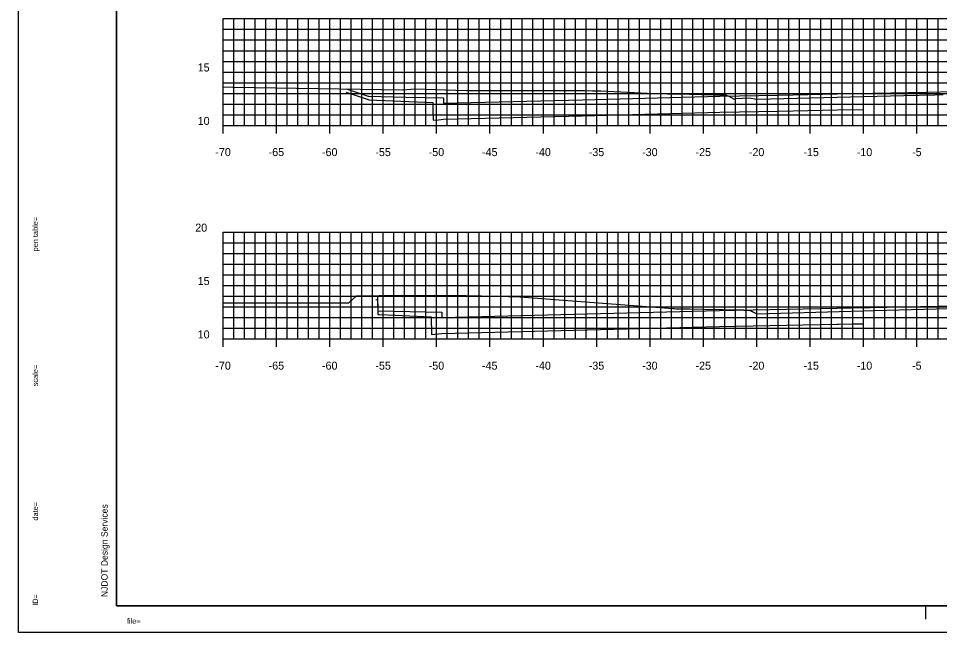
# Model space of a CAD drawing. Extents: x 40011 to 50684, y 49949 to 72236.
# Drawn here: x 42164.4 to 42250.7, y 68071.1 to 68128.6 of the extents above; entities that cross this region are included whole.
import ezdxf

# ---------------------------------------------------------------- set-up
doc = ezdxf.new("R2010")
doc.units = 0
for name, color, linetype in [('1', 7, 'Continuous'), ('41', 7, 'Continuous'), ('51', 7, 'Continuous'), ('52', 7, 'Continuous'), ('53', 7, 'Continuous'), ('54', 7, 'Continuous'), ('55', 7, 'Continuous'), ('57', 7, 'Continuous'), ('58', 7, 'Continuous'), ('59', 7, 'Continuous')]:
    doc.layers.add(name, color=color, linetype=linetype)

msp = doc.modelspace()

# ---------------------------------------------------------------- linework, layer by layer
at = {"layer": '1'}
for p, q in [((42173.586, 68178.597), (42173.586, 68073.597)), ((42173.586, 68073.597), (42338.586, 68073.597)), ((42249.42, 68072.347), (42249.42, 68073.597)), ((42339.087, 68071.097), (42164.392, 68071.097))]:
    msp.add_line(p, q, dxfattribs=at)
at = {"layer": '41'}
for points in [[(42164.392, 68181.097), (42339.087, 68181.097), (42339.087, 68071.097), (42164.392, 68071.097)], [(42173.586, 68178.597), (42338.586, 68178.597), (42338.586, 68073.597), (42173.586, 68073.597)]]:
    msp.add_lwpolyline(points, close=True, dxfattribs=at)
at = {"layer": '51'}
for p, q in [((42183.586, 68118.597), (42183.586, 68128.597)), ((42183.586, 68128.597), (42184.336, 68128.597)), ((42183.586, 68123.597), (42184.336, 68123.597)), ((42183.586, 68118.597), (42184.336, 68118.597)), ((42183.586, 68098.597), (42183.586, 68108.597)), ((42183.586, 68108.597), (42184.336, 68108.597)), ((42183.586, 68103.597), (42184.336, 68103.597)), ((42183.586, 68098.597), (42184.336, 68098.597))]:
    msp.add_line(p, q, dxfattribs=at)
at = {"layer": '52'}
for p, q in [((42183.586, 68118.597), (42323.586, 68118.597)), ((42183.586, 68117.847), (42183.586, 68118.597)), ((42188.586, 68117.847), (42188.586, 68118.597)), ((42193.586, 68117.847), (42193.586, 68118.597)), ((42198.586, 68117.847), (42198.586, 68118.597)), ((42203.586, 68117.847), (42203.586, 68118.597)), ((42208.586, 68117.847), (42208.586, 68118.597)), ((42213.586, 68117.847), (42213.586, 68118.597)), ((42218.586, 68117.847), (42218.586, 68118.597)), ((42223.586, 68117.847), (42223.586, 68118.597)), ((42228.586, 68117.847), (42228.586, 68118.597)), ((42233.586, 68117.847), (42233.586, 68118.597)), ((42238.586, 68117.847), (42238.586, 68118.597)), ((42243.586, 68117.847), (42243.586, 68118.597)), ((42248.586, 68117.847), (42248.586, 68118.597)), ((42183.586, 68098.597), (42323.586, 68098.597)), ((42183.586, 68097.847), (42183.586, 68098.597)), ((42188.586, 68097.847), (42188.586, 68098.597)), ((42193.586, 68097.847), (42193.586, 68098.597)), ((42198.586, 68097.847), (42198.586, 68098.597)), ((42203.586, 68097.847), (42203.586, 68098.597)), ((42208.586, 68097.847), (42208.586, 68098.597)), ((42213.586, 68097.847), (42213.586, 68098.597)), ((42218.586, 68097.847), (42218.586, 68098.597)), ((42223.586, 68097.847), (42223.586, 68098.597)), ((42228.586, 68097.847), (42228.586, 68098.597)), ((42233.586, 68097.847), (42233.586, 68098.597)), ((42238.586, 68097.847), (42238.586, 68098.597)), ((42243.586, 68097.847), (42243.586, 68098.597)), ((42248.586, 68097.847), (42248.586, 68098.597))]:
    msp.add_line(p, q, dxfattribs=at)
at = {"layer": '53'}
for p, q in [((42183.586, 68127.597), (42323.586, 68127.597)), ((42183.586, 68126.597), (42323.586, 68126.597)), ((42183.586, 68125.597), (42323.586, 68125.597)), ((42183.586, 68124.597), (42323.586, 68124.597)), ((42183.586, 68122.597), (42323.586, 68122.597)), ((42183.586, 68121.597), (42323.586, 68121.597)), ((42183.586, 68120.597), (42323.586, 68120.597)), ((42183.586, 68119.597), (42323.586, 68119.597)), ((42183.586, 68107.597), (42323.586, 68107.597)), ((42183.586, 68106.597), (42323.586, 68106.597)), ((42183.586, 68105.597), (42323.586, 68105.597)), ((42183.586, 68104.597), (42323.586, 68104.597)), ((42183.586, 68102.597), (42323.586, 68102.597)), ((42183.586, 68101.597), (42323.586, 68101.597)), ((42183.586, 68100.597), (42323.586, 68100.597)), ((42183.586, 68099.597), (42323.586, 68099.597))]:
    msp.add_line(p, q, dxfattribs=at)
at = {"layer": '54'}
for p, q in [((42184.586, 68118.597), (42184.586, 68128.597)), ((42185.586, 68118.597), (42185.586, 68128.597)), ((42186.586, 68118.597), (42186.586, 68128.597)), ((42187.586, 68118.597), (42187.586, 68128.597)), ((42189.586, 68118.597), (42189.586, 68128.597)), ((42190.586, 68118.597), (42190.586, 68128.597)), ((42191.586, 68118.597), (42191.586, 68128.597)), ((42192.586, 68118.597), (42192.586, 68128.597)), ((42194.586, 68118.597), (42194.586, 68128.597)), ((42195.586, 68118.597), (42195.586, 68128.597)), ((42196.586, 68118.597), (42196.586, 68128.597)), ((42197.586, 68118.597), (42197.586, 68128.597)), ((42199.586, 68118.597), (42199.586, 68128.597)), ((42200.586, 68118.597), (42200.586, 68128.597)), ((42201.586, 68118.597), (42201.586, 68128.597)), ((42202.586, 68118.597), (42202.586, 68128.597)), ((42204.586, 68118.597), (42204.586, 68128.597)), ((42205.586, 68118.597), (42205.586, 68128.597)), ((42206.586, 68118.597), (42206.586, 68128.597)), ((42207.586, 68118.597), (42207.586, 68128.597)), ((42209.586, 68118.597), (42209.586, 68128.597)), ((42210.586, 68118.597), (42210.586, 68128.597)), ((42211.586, 68118.597), (42211.586, 68128.597)), ((42212.586, 68118.597), (42212.586, 68128.597)), ((42214.586, 68118.597), (42214.586, 68128.597)), ((42215.586, 68118.597), (42215.586, 68128.597)), ((42216.586, 68118.597), (42216.586, 68128.597)), ((42217.586, 68118.597), (42217.586, 68128.597)), ((42219.586, 68118.597), (42219.586, 68128.597)), ((42220.586, 68118.597), (42220.586, 68128.597)), ((42221.586, 68118.597), (42221.586, 68128.597)), ((42222.586, 68118.597), (42222.586, 68128.597)), ((42224.586, 68118.597), (42224.586, 68128.597)), ((42225.586, 68118.597), (42225.586, 68128.597)), ((42226.586, 68118.597), (42226.586, 68128.597)), ((42227.586, 68118.597), (42227.586, 68128.597)), ((42229.586, 68118.597), (42229.586, 68128.597)), ((42230.586, 68118.597), (42230.586, 68128.597)), ((42231.586, 68118.597), (42231.586, 68128.597)), ((42232.586, 68118.597), (42232.586, 68128.597)), ((42234.586, 68118.597), (42234.586, 68128.597)), ((42235.586, 68118.597), (42235.586, 68128.597)), ((42236.586, 68118.597), (42236.586, 68128.597)), ((42237.586, 68118.597), (42237.586, 68128.597)), ((42239.586, 68118.597), (42239.586, 68128.597)), ((42240.586, 68118.597), (42240.586, 68128.597)), ((42241.586, 68118.597), (42241.586, 68128.597)), ((42242.586, 68118.597), (42242.586, 68128.597)), ((42244.586, 68118.597), (42244.586, 68128.597)), ((42245.586, 68118.597), (42245.586, 68128.597)), ((42246.586, 68118.597), (42246.586, 68128.597)), ((42247.586, 68118.597), (42247.586, 68128.597)), ((42249.586, 68118.597), (42249.586, 68128.597)), ((42250.586, 68118.597), (42250.586, 68128.597)), ((42184.586, 68098.597), (42184.586, 68108.597)), ((42185.586, 68098.597), (42185.586, 68108.597)), ((42186.586, 68098.597), (42186.586, 68108.597)), ((42187.586, 68098.597), (42187.586, 68108.597)), ((42189.586, 68098.597), (42189.586, 68108.597)), ((42190.586, 68098.597), (42190.586, 68108.597)), ((42191.586, 68098.597), (42191.586, 68108.597)), ((42192.586, 68098.597), (42192.586, 68108.597)), ((42194.586, 68098.597), (42194.586, 68108.597)), ((42195.586, 68098.597), (42195.586, 68108.597)), ((42196.586, 68098.597), (42196.586, 68108.597)), ((42197.586, 68098.597), (42197.586, 68108.597)), ((42199.586, 68098.597), (42199.586, 68108.597)), ((42200.586, 68098.597), (42200.586, 68108.597)), ((42201.586, 68098.597), (42201.586, 68108.597)), ((42202.586, 68098.597), (42202.586, 68108.597)), ((42204.586, 68098.597), (42204.586, 68108.597)), ((42205.586, 68098.597), (42205.586, 68108.597)), ((42206.586, 68098.597), (42206.586, 68108.597)), ((42207.586, 68098.597), (42207.586, 68108.597)), ((42209.586, 68098.597), (42209.586, 68108.597)), ((42210.586, 68098.597), (42210.586, 68108.597)), ((42211.586, 68098.597), (42211.586, 68108.597)), ((42212.586, 68098.597), (42212.586, 68108.597)), ((42214.586, 68098.597), (42214.586, 68108.597)), ((42215.586, 68098.597), (42215.586, 68108.597)), ((42216.586, 68098.597), (42216.586, 68108.597)), ((42217.586, 68098.597), (42217.586, 68108.597)), ((42219.586, 68098.597), (42219.586, 68108.597)), ((42220.586, 68098.597), (42220.586, 68108.597)), ((42221.586, 68098.597), (42221.586, 68108.597)), ((42222.586, 68098.597), (42222.586, 68108.597)), ((42224.586, 68098.597), (42224.586, 68108.597)), ((42225.586, 68098.597), (42225.586, 68108.597)), ((42226.586, 68098.597), (42226.586, 68108.597)), ((42227.586, 68098.597), (42227.586, 68108.597)), ((42229.586, 68098.597), (42229.586, 68108.597)), ((42230.586, 68098.597), (42230.586, 68108.597)), ((42231.586, 68098.597), (42231.586, 68108.597)), ((42232.586, 68098.597), (42232.586, 68108.597)), ((42234.586, 68098.597), (42234.586, 68108.597)), ((42235.586, 68098.597), (42235.586, 68108.597)), ((42236.586, 68098.597), (42236.586, 68108.597)), ((42237.586, 68098.597), (42237.586, 68108.597)), ((42239.586, 68098.597), (42239.586, 68108.597)), ((42240.586, 68098.597), (42240.586, 68108.597)), ((42241.586, 68098.597), (42241.586, 68108.597)), ((42242.586, 68098.597), (42242.586, 68108.597)), ((42244.586, 68098.597), (42244.586, 68108.597)), ((42245.586, 68098.597), (42245.586, 68108.597)), ((42246.586, 68098.597), (42246.586, 68108.597)), ((42247.586, 68098.597), (42247.586, 68108.597)), ((42249.586, 68098.597), (42249.586, 68108.597)), ((42250.586, 68098.597), (42250.586, 68108.597))]:
    msp.add_line(p, q, dxfattribs=at)
at = {"layer": '55'}
for p, q in [((42183.586, 68128.597), (42323.586, 68128.597)), ((42183.586, 68118.597), (42183.586, 68128.597)), ((42188.586, 68118.597), (42188.586, 68128.597)), ((42193.586, 68118.597), (42193.586, 68128.597)), ((42198.586, 68118.597), (42198.586, 68128.597)), ((42203.586, 68118.597), (42203.586, 68128.597)), ((42208.586, 68118.597), (42208.586, 68128.597)), ((42213.586, 68118.597), (42213.586, 68128.597)), ((42218.586, 68118.597), (42218.586, 68128.597)), ((42223.586, 68118.597), (42223.586, 68128.597)), ((42228.586, 68118.597), (42228.586, 68128.597)), ((42233.586, 68118.597), (42233.586, 68128.597)), ((42238.586, 68118.597), (42238.586, 68128.597)), ((42243.586, 68118.597), (42243.586, 68128.597)), ((42248.586, 68118.597), (42248.586, 68128.597)), ((42183.586, 68123.597), (42323.586, 68123.597)), ((42183.586, 68118.597), (42323.586, 68118.597)), ((42183.586, 68108.597), (42323.586, 68108.597)), ((42183.586, 68098.597), (42183.586, 68108.597)), ((42188.586, 68098.597), (42188.586, 68108.597)), ((42193.586, 68098.597), (42193.586, 68108.597)), ((42198.586, 68098.597), (42198.586, 68108.597)), ((42203.586, 68098.597), (42203.586, 68108.597)), ((42208.586, 68098.597), (42208.586, 68108.597)), ((42213.586, 68098.597), (42213.586, 68108.597)), ((42218.586, 68098.597), (42218.586, 68108.597)), ((42223.586, 68098.597), (42223.586, 68108.597)), ((42228.586, 68098.597), (42228.586, 68108.597)), ((42233.586, 68098.597), (42233.586, 68108.597)), ((42238.586, 68098.597), (42238.586, 68108.597)), ((42243.586, 68098.597), (42243.586, 68108.597)), ((42248.586, 68098.597), (42248.586, 68108.597)), ((42183.586, 68103.597), (42323.586, 68103.597)), ((42183.586, 68098.597), (42323.586, 68098.597))]:
    msp.add_line(p, q, dxfattribs=at)
at = {"layer": '57'}
for points in [[(42183.586, 68122.2), (42184.498, 68122.18), (42200.409, 68121.938), (42201.557, 68122.016), (42206.36, 68121.862), (42217.207, 68121.872), (42217.453, 68121.867), (42218.19, 68121.85), (42218.986, 68121.827), (42223.355, 68121.631), (42225.219, 68121.57), (42226.166, 68121.544), (42229.545, 68121.474), (42230.688, 68121.476), (42230.963, 68121.328), (42231.468, 68121.063), (42231.583, 68121.111), (42232.893, 68121.187), (42233.551, 68121.044), (42233.619, 68121.041), (42247.363, 68121.385), (42250.28, 68121.459), (42251.047, 68121.477)], [(42183.586, 68101.991), (42194.195, 68101.977), (42194.824, 68101.976), (42195.352, 68101.965), (42195.37, 68101.975), (42196.084, 68102.637), (42200.287, 68102.685), (42206.344, 68102.658), (42209.228, 68102.611), (42209.624, 68102.603), (42210.034, 68102.595), (42210.324, 68102.587), (42210.967, 68102.562), (42225.734, 68101.446), (42225.782, 68101.445), (42225.887, 68101.44), (42226.016, 68101.433), (42226.128, 68101.427), (42226.518, 68101.414), (42227.311, 68101.404), (42228.57, 68101.384), (42232.341, 68101.311), (42232.36, 68101.303), (42232.869, 68101.273), (42232.908, 68101.289), (42233.583, 68100.964), (42233.638, 68100.95), (42244.607, 68101.249), (42252.72, 68101.477)]]:
    msp.add_lwpolyline(points, dxfattribs=at)
at = {"layer": '58'}
for points in [[(42195.109, 68121.699), (42197.17, 68121.012), (42197.234, 68120.99), (42200.237, 68120.872), (42203.238, 68120.755), (42203.243, 68119.923), (42203.248, 68119.086), (42203.746, 68119.132), (42204.244, 68119.179), (42217.244, 68119.504), (42230.13, 68119.826), (42235.63, 68119.936), (42241.131, 68120.047), (42243.581, 68120.096), (42243.587, 68120.096)], [(42197.894, 68102.296), (42198.003, 68102.264), (42198.048, 68102.329), (42198.076, 68100.897), (42198.231, 68100.89), (42199.708, 68100.826), (42203.081, 68100.681), (42203.09, 68099.012), (42204.086, 68099.106), (42230.086, 68099.756), (42241.086, 68099.976), (42241.313, 68099.98), (42242.578, 68100.006), (42243.53, 68100.025), (42243.586, 68100.026), (42243.586, 68100.026), (42243.587, 68100.026)]]:
    msp.add_lwpolyline(points, dxfattribs=at)
at = {"layer": '59'}
for points in [[(42195.11, 68122.029), (42197.17, 68121.342), (42197.234, 68121.321), (42200.734, 68121.251), (42204.234, 68121.181), (42204.239, 68120.931), (42204.244, 68120.681), (42217.244, 68121.006), (42230.13, 68121.328), (42235.63, 68121.438), (42241.132, 68121.548), (42249.481, 68121.715), (42252.086, 68121.767)], [(42198.048, 68102.659), (42198.076, 68101.227), (42204.076, 68101.107), (42204.086, 68100.607), (42230.086, 68101.257), (42241.086, 68101.477), (42252.077, 68101.697), (42252.223, 68102.194), (42252.239, 68102.194), (42254.085, 68102.163), (42255.926, 68102.132), (42255.931, 68102.132), (42256.077, 68101.63), (42259.086, 68101.584), (42270.086, 68101.364), (42284.743, 68100.998), (42284.753, 68101.498), (42291.753, 68101.638), (42291.756, 68101.638), (42294.737, 68101.696), (42294.741, 68101.536), (42294.747, 68101.196)]]:
    msp.add_lwpolyline(points, dxfattribs=at)

# ---------------------------------------------------------------- texts
at = {"layer": '1'}
for s, height, rotation, p in [('...................pentable..................', 0.0072, 90, (42166.224, 68110.775)), ('pen table=', 0.5, 90, (42166.224, 68106.791)), ('......scale......', 0.0072, 90, (42166.224, 68096.608)), ('scale=', 0.5, 90, (42166.224, 68094.163)), ('.......time......', 0.0072, 90, (42166.224, 68083.775)), ('date=', 0.5, 90, (42166.224, 68081.587)), ('NJDOT Design Services', 0.6, 90, (42172.753, 68074.419)), ('............who............', 0.0072, 90, (42166.224, 68074.93)), ('ID=', 0.5, 90, (42166.224, 68073.601)), ('file=', 0.5, 360, (42174.56, 68071.93)), ('...................bob..................', 0.0072, 360, (42176.224, 68071.93))]:
    msp.add_text(s, height=height, rotation=rotation, dxfattribs=at).set_placement(p)
at = {"layer": '51'}
for s, height, p in [('15', 0.75, (42181.193, 68123.647)), ('10', 0.75, (42181.193, 68118.647)), ('-', 0.0001, (42183.586, 68118.597)), ('20', 0.75, (42180.966, 68108.647)), ('15', 0.75, (42181.193, 68103.647)), ('10', 0.75, (42181.193, 68098.647)), ('-', 0.0001, (42183.586, 68098.597))]:
    msp.add_text(s, height=height, dxfattribs=at).set_placement(p)
at = {"layer": '52'}
for s, p in [('-70', (42182.847, 68115.722)), ('-65', (42187.841, 68115.722)), ('-60', (42192.841, 68115.722)), ('-55', (42197.843, 68115.722)), ('-50', (42202.843, 68115.722)), ('-45', (42207.838, 68115.722)), ('-40', (42212.838, 68115.722)), ('-35', (42217.843, 68115.722)), ('-30', (42222.843, 68115.722)), ('-25', (42227.847, 68115.722)), ('-20', (42232.847, 68115.722)), ('-15', (42237.96, 68115.722)), ('-10', (42242.96, 68115.722)), ('-5', (42248.145, 68115.722)), ('-70', (42182.847, 68095.722)), ('-65', (42187.841, 68095.722)), ('-60', (42192.841, 68095.722)), ('-55', (42197.843, 68095.722)), ('-50', (42202.843, 68095.722)), ('-45', (42207.838, 68095.722)), ('-40', (42212.838, 68095.722)), ('-35', (42217.843, 68095.722)), ('-30', (42222.843, 68095.722)), ('-25', (42227.847, 68095.722)), ('-20', (42232.847, 68095.722)), ('-15', (42237.96, 68095.722)), ('-10', (42242.96, 68095.722)), ('-5', (42248.145, 68095.722))]:
    msp.add_text(s, height=0.75, dxfattribs=at).set_placement(p)

doc.saveas('drawing.dxf')
